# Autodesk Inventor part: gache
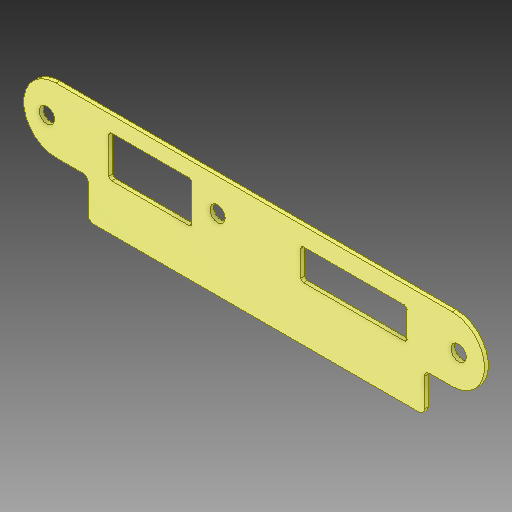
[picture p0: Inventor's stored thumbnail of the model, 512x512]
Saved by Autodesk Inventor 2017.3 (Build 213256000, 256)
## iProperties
Created: 2011-01
Part Number: gache
Material: Générique
Document SubType Name: Modeling
Designer: ficho
Density: 1 g/cm^3
Appearance: Par défaut
Author: ficho
Sending System: SolidWorks 2009
Last Author: christophe
Last Saved: 2011-02-10
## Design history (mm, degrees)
extrude "Extrusion1"
node "Solide1"
